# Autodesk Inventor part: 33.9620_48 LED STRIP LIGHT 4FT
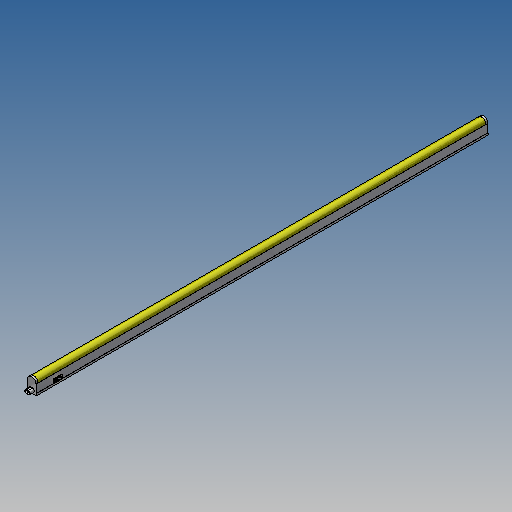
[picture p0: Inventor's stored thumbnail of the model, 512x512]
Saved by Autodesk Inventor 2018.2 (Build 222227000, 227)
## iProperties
Created: 2017-10
Part Number: 33.9620_48 LED STRIP LIGHT 4FT
Material: Generic
Document SubType Name: Modeling
Designer: Admin
Density: 1 g/cm^3
Appearance: Snow
Author: Admin
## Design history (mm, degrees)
sketch "Sketch1"
  geometry: L1 (11, 0)-(-11, 0); L2 (-11, 0)-(-11, -25.332); L3 (-11, -25.332)-(11, -25.332); L4 (11, -25.332)-(11, 0); L5 (-11.5, -20.332)-(11.5, -20.332); L6 (11.5, -20.332)-(11.5, -25.332); L7 (11.5, -25.332)-(-11.5, -25.332); L8 (-11.5, -25.332)-(-11.5, -20.332); C1 r 10.668 at (0, 0); 4 further points
  constraints: 16 end point, 4 coincident, 4 parallel, 3 midpoint, 2 horizontal, 2 perpendicular, 1 centre point
  dimensions: "d0" = 21.336 diameter of C1; "d1" = 22 distance of L2.end L3.end; "d2" = 36 dimension on C1 L3; "d5" = 0 distance between parallel lines of L3 L7; "d6" = 23 distance of L5.start L5.end; "d7" = 5 distance between parallel lines of L3 L5
extrude "Extrusion1" new body sketch "Sketch1" stored distance "d3" = 1126.64; taper "d4" = 0 deg
sketch "Sketch2"
  geometry: L1 (-11, 0)-(-10.668, 0) reference; L2 (-11, -20.332)-(-11, 0) reference; L3 (11.5, -25.332)-(-11.5, -25.332) reference; L4 (11, 0)-(11, -20.332) reference; L5 (10.668, 0)-(11, 0) reference; L6 (-11.5, -25.332)-(-11.5, -20.332) reference; L7 (11.5, -20.332)-(11.5, -25.332) reference; L8 (11, -20.332)-(11.5, -20.332) reference; L9 (-11, 0)-(-10.668, 0) reference; L10 (-11, -20.332)-(-11, 0) reference; L11 (-11.5, -20.332)-(-11, -20.332) reference; L12 (-11.5, -25.332)-(-11.5, -20.332) reference; L13 (11.5, -25.332)-(-11.5, -25.332) reference; L14 (11.5, -20.332)-(11.5, -25.332) reference; L15 (11, -20.332)-(11.5, -20.332) reference; L16 (11, 0)-(11, -20.332) reference; L17 (10.668, 0)-(11, 0) reference; A1 r 10.668 centre (0, 0) between (10.668, 0) and (-10.668, 0) reference; A2 r 11 centre (0, 0) between (11, 0) and (-11, 0); A3 r 10.668 centre (0, 0) between (10.668, 0) and (-10.668, 0) reference
  constraints: 2 end point, 2 point on circle, 1 centre point, 1 coincident, 1 tangent
extrude "Extrusion2" join sketch "Sketch2" distance "d8" = 5; taper "d9" = 0 deg
mirror "Mirror1"
sketch "Sketch3"
  geometry: L1 (-2.2, -12.732)-(2.2, -12.732); L2 (2.2, -21.932)-(-2.2, -21.932); L3 (2.2, -13.932)-(-2.2, -13.932); L4 (-2.2, -20.732)-(2.2, -20.732); L5 (-11.5, -25.332)-(11.5, -25.332) reference; A1 r 4.6 centre (-2.2, -17.332) between (-2.2, -12.732) and (-2.2, -21.932); A2 r 4.6 centre (2.2, -17.332) between (2.2, -21.932) and (2.2, -12.732); A3 r 3.4 centre (-2.2, -17.332) between (-2.2, -13.932) and (-2.2, -20.732); A4 r 3.4 centre (2.2, -17.332) between (2.2, -20.732) and (2.2, -13.932); 2 further points
  constraints: 8 end point, 8 point on circle, 4 centre point, 2 midpoint, 2 parallel, 2 tangent, 1 equal radius, 1 horizontal, 1 horizontal alignment, 1 vertical alignment, 3 other
  dimensions: "d11" = 9.2 distance between parallel lines of L2 L1; "d12" = 13.6 dimension on A2 A1; "d13" = 1.2 distance between parallel lines of L3 L1; "d22" = 8 distance from line of A2.centre L5
extrude "Extrusion3" join sketch "Sketch3" distance "d14" = 10.8; taper "d15" = 0 deg
sketch "Sketch4"
  geometry: C1 r 0.75 at (-2.2, -17.332); C2 r 0.75 at (2.2, -17.332); A1 r 3.4 centre (2.2, -17.332) between (2.2, -20.732) and (2.2, -13.932) reference; A2 r 3.4 centre (-2.2, -17.332) between (-2.2, -13.932) and (-2.2, -20.732) reference; 1 further point
  constraints: 2 centre point, 2 coincident, 1 equal radius
  dimensions: "d16" = 1.5 diameter of C2
extrude "Extrusion4" join sketch "Sketch4" distance "d17" = 9.4; taper "d18" = 0 deg
fillet "Fillet1" dims "d19" = 0.75
sketch "Sketch5"
  geometry: L1 (-2.2, -20.732)-(2.2, -20.732) reference; L2 (2.2, -13.932)-(-2.2, -13.932) reference; L3 (2.2, -21.932)-(-2.2, -21.932) reference; L4 (-2.2, -12.732)-(2.2, -12.732) reference; C1 r 0.75 at (2.2, -17.332) reference; C2 r 0.75 at (-2.2, -17.332) reference; A1 r 3.4 centre (-2.2, -17.332) between (-2.2, -13.932) and (-2.2, -20.732) reference; A2 r 3.4 centre (2.2, -17.332) between (2.2, -20.732) and (2.2, -13.932) reference; A3 r 4.6 centre (2.2, -17.332) between (2.2, -21.932) and (2.2, -12.732) reference; A4 r 4.6 centre (-2.2, -17.332) between (-2.2, -12.732) and (-2.2, -21.932) reference
extrude "Extrusion5" cut sketch "Sketch5" distance "d20" = 10.8; taper "d21" = 0 deg
sketch "Sketch6"
  geometry: L1 (1136.64, 0)-(0, 0) reference; L2 (0, 0)-(0, 20.332) reference; L3 (44, 10)-(65, 10); L4 (65, 10)-(65, 0.5); L5 (65, 0.5)-(44, 0.5); L6 (44, 0.5)-(44, 10); L7 (49.75, 8)-(59.25, 8); L8 (59.25, 2.5)-(49.75, 2.5); A1 r 2.75 centre (49.75, 5.25) between (49.75, 8) and (49.75, 2.5); A2 r 2.75 centre (59.25, 5.25) between (59.25, 2.5) and (59.25, 8); 4 further points
  constraints: 12 end point, 4 point on circle, 3 midpoint, 3 parallel, 2 centre point, 2 horizontal, 2 horizontal alignment, 2 tangent, 1 equal radius, 1 perpendicular, 1 vertical alignment
  dimensions: "d23" = 9.5 distance of L5.end L3.start; "d24" = 0.5 distance between parallel lines of L5 L1; "d25" = 21 distance of L3.start L3.end; "d26" = 44 distance between parallel lines of L6 L2; "d27" = 5.5 distance between parallel lines of L8 L7; "d28" = 15 dimension on A2 A1
extrude "Extrusion6" join sketch "Sketch6" distance "d29" = 1.55; taper "d30" = 0 deg
workplane "Work Plane1"
sketch "Sketch7"
  geometry: L1 (0, -5.75)-(0, 15.25) reference; L2 (0, -2.25)-(3.5, -2.25); L3 (3.5, -2.25)-(3.5, 11.75); L4 (3.5, 11.75)-(0, 11.75); L5 (0, 11.75)-(0, -2.25); L6 (1.55, 0)-(1.55, -2.75) reference; L7 (1.55, 12.25)-(1.55, 9.5) reference; A1 r 12.964 centre (14.411, 4.75) between (3.5, 11.75) and (3.5, -2.25); 1 further point
  constraints: 8 end point, 2 parallel, 2 point on circle, 1 centre point, 1 horizontal, 1 perpendicular, 1 point on line
  dimensions: "d31" = 0.5 distance from line of L6.end L2; "d32" = 0.5 distance from line of L4 L7.start; "d33" = 3.5 distance between parallel lines of L3 L1
extrude "Extrusion7" join sketch "Sketch7" stored distance "d34" = 4; taper "d35" = 0 deg
fillet "Fillet2" dims "d36" = 0.75
body "Solid1"
node "Projected Loop1"
node "Projected Loop2"
node "Projected Loop3"
node "Projected Loop4"
